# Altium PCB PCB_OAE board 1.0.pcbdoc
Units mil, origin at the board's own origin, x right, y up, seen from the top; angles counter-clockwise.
Board outline 3923.56 x 3666.58 mil, 2 copper layers (Top Layer, Bottom Layer); 47 components, 66 nets, 220 pads, 117 vias.
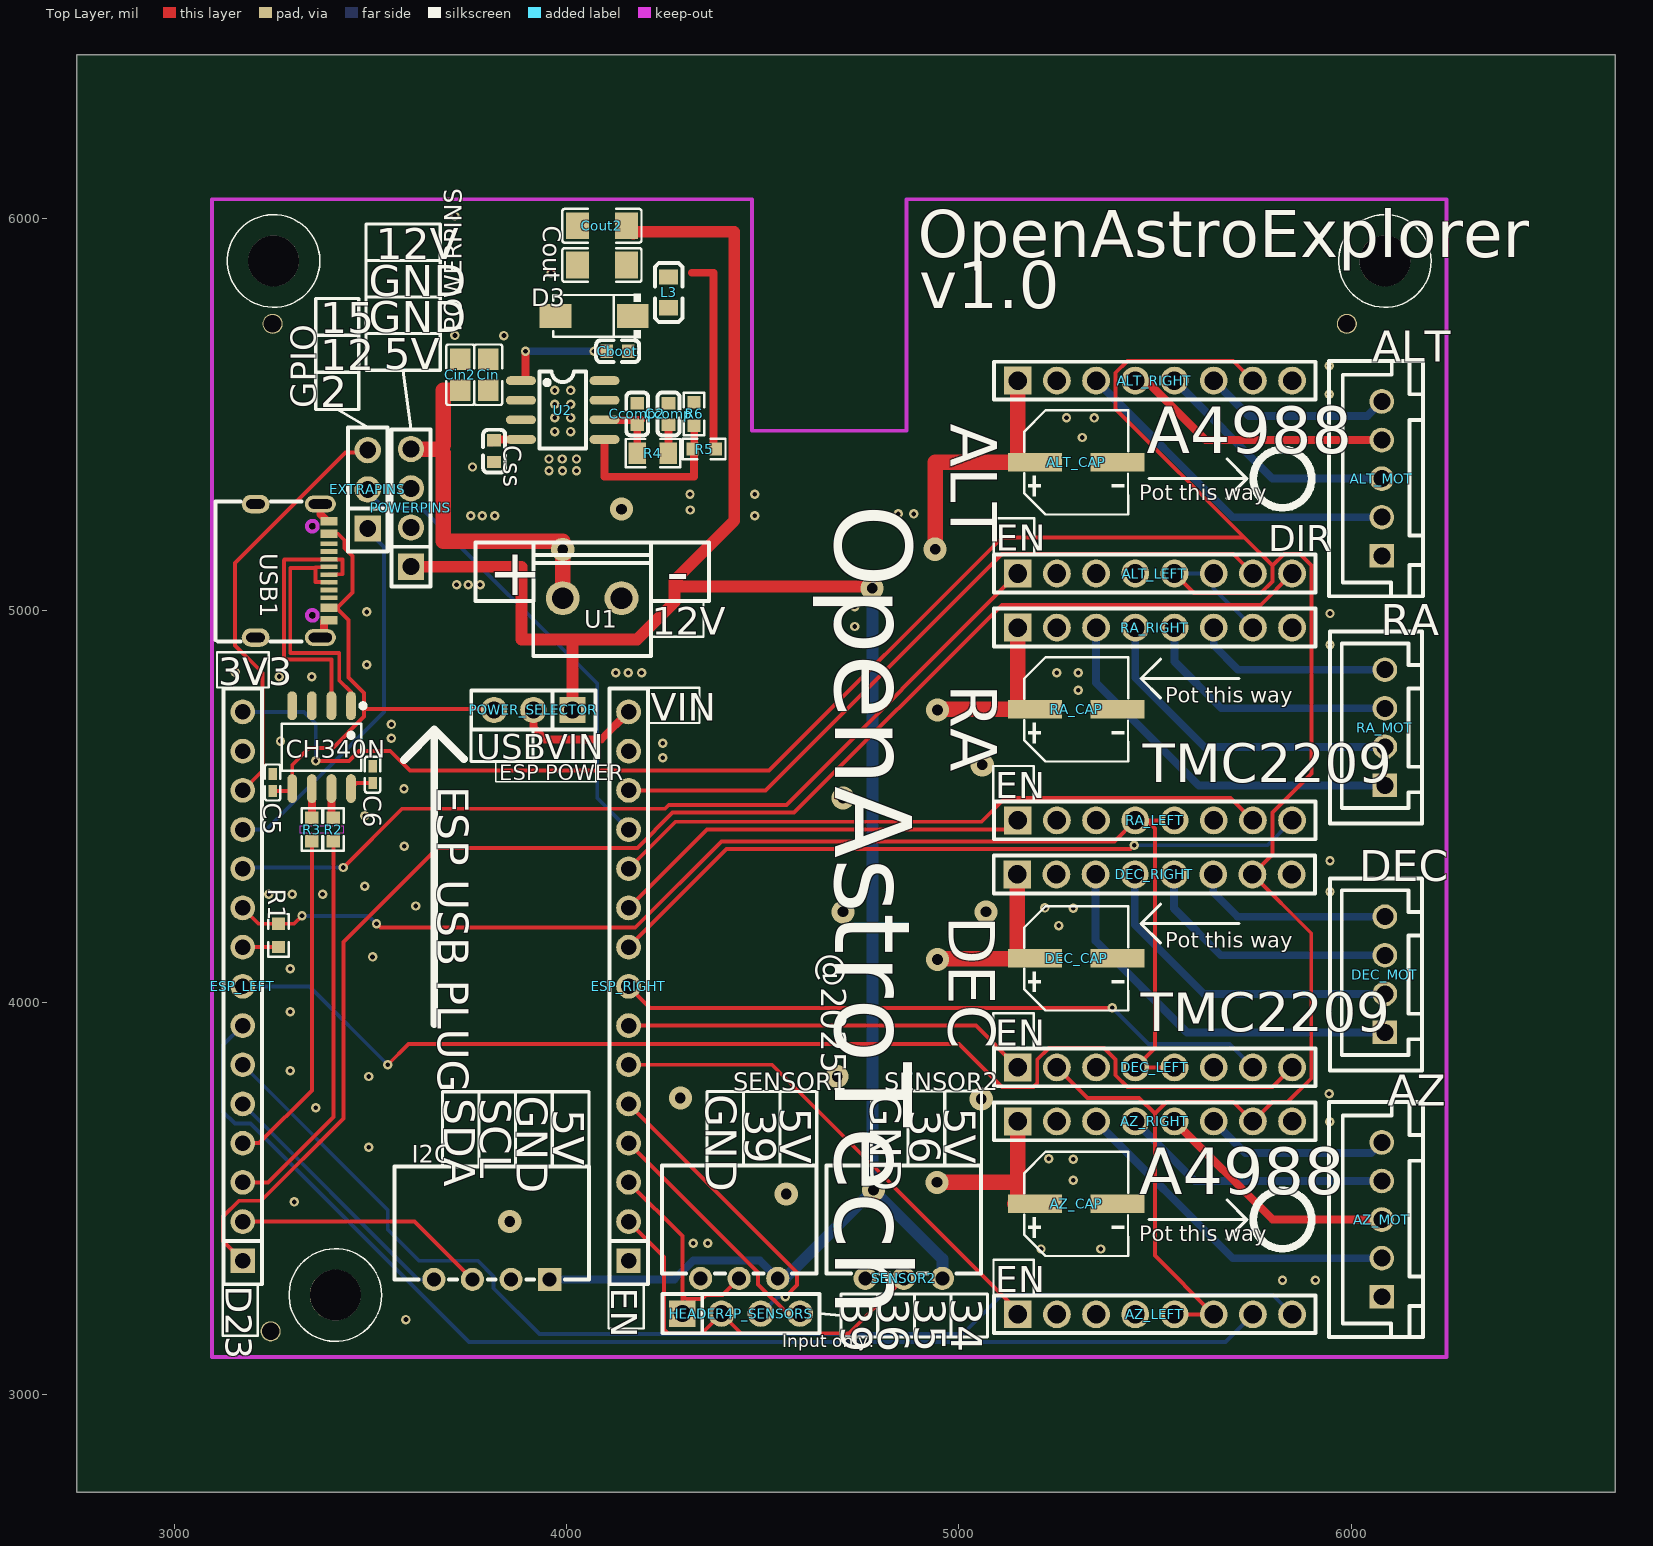
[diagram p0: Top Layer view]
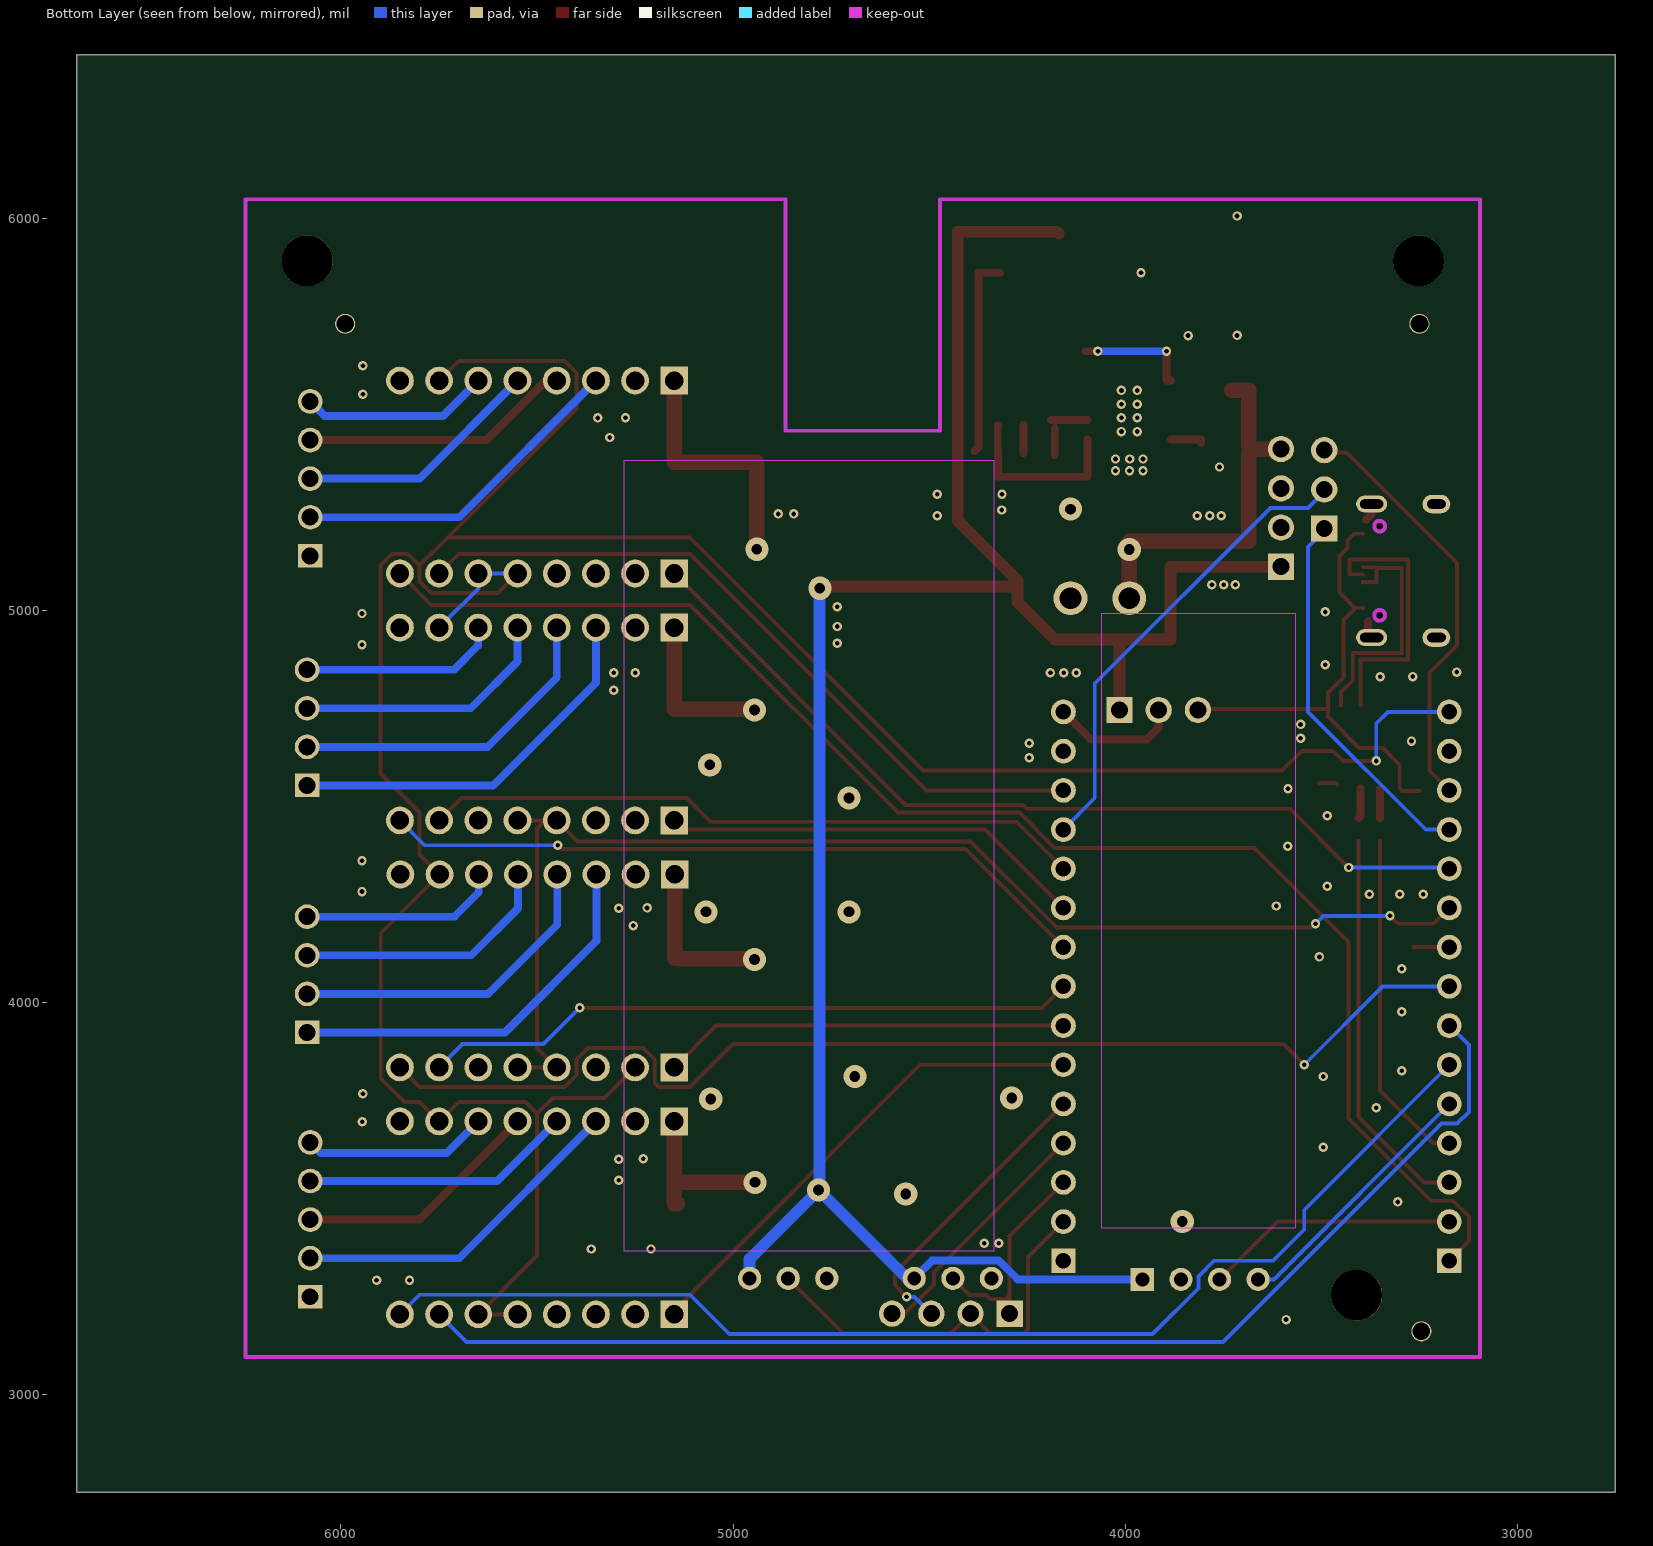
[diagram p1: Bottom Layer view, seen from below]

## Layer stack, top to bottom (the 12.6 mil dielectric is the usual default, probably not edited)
Top Layer: signal copper (thickness not stored)
Dielectric: dielectric 12.6, FR-4, Dk 4.8
Bottom Layer: signal copper (thickness not stored)

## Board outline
6673.56,2750 2750,2750 2750,6416.58 6673.56,6416.58

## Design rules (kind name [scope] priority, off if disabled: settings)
BoardOutlineClearance safeClearance [All] p0: genericclearance=10 ignorepadtopadclearanceinfootprint=FALSE except(0: Arc-SplitContinuation Track-SplitContinuation SMDPad-SplitContinuation THPad-SplitContinuation Via-SplitContinuation Fill-SplitContinuation Poly-SplitContinuation Region-SplitContinuation Text-SplitContinuation; 6: Track-CutoutEdge SMDPad-CutoutEdge THPad-CutoutEdge Via-CutoutEdge Fill-CutoutEdge Region-CutoutEdge; 11.8: Track-OutlineEdge SMDPad-OutlineEdge THPad-OutlineEdge Via-OutlineEdge Fill-OutlineEdge Region-OutlineEdge Poly-OutlineEdge Text-OutlineEdge)
Clearance safeClearance [(InNet('DEC_DIR') OR InNet('5V2A') OR InNet('ALT_EN') OR InNet('AZ_B2') OR InNet('AZ_A1') OR InNet('ALT_A1') OR InNet('ALT_B1') OR InNet('DEC_EN') OR InNet('AZ_DIR') OR InNet('ALT_DIR') OR InNet('DEC_STEP') OR InNet('AZ_EN') OR InNet('ALT_STEP') OR InNet('ESPRX') OR InNet('ESPTX') OR InNet('USBDP') OR InNet('AZ_A2') OR InNet('AZ_B1') OR InNet('ALT_B2') OR InNet('ALT_A2') OR InNet('DEC_B2') OR InNet('DEC_B1') OR InNet('DEC_A1') OR InNet('DEC_A2') OR InNet('RA_B1') OR InNet('RA_A2') OR InNet('RA_A1') OR InNet('RA_B2') OR InNet('USB5V') OR InNet('USBDN') OR InNet('ALT_MS1') OR InNet('ALT_MS2') OR InNet('ALT_MS3') OR InNet('AZ_MS1') OR InNet('AZ_MS2') OR InNet('AZ_MS3') OR InNet('DEC_CLK') OR InNet('RA_CLK') OR InNet('GPIO15') OR InNet('GPIO2') OR InNet('GPIO12') OR InNet('GPIO35') OR InNet('GPIO34') OR InNet('GPIO39') OR InNet('GPIO36') OR InNet('ESP_EN') OR InNet('AZ_STEP') OR InNet('$1N15') OR InNet('DEC_UART1') OR InNet('$1N26') OR InNet('$1N27') OR InNet('GND') OR InNet('PSU12V') OR InNet('ESPVOUT') OR InNet('GPIO17') OR InNet('GPIO21') OR InNet('GPIO22') OR InNet('$1N13245') OR InNet('$1N13249') OR InNet('$1N12989') OR InNet('$1N13607') OR InNet('$1N13151') OR InNet('$1N13891') OR InNet('GPIO14') OR InNet('GPIO26') OR InNet('GPIO27'))] p1: gap=7 ignorepadtopadclearanceinfootprint=FALSE except(6: Track-Track SMDPad-SMDPad Track-THPad SMDPad-THPad THPad-THPad Track-Via SMDPad-Via THPad-Via Via-Via Track-Fill SMDPad-Fill THPad-Fill Via-Fill Fill-Fill Track-Region SMDPad-Region THPad-Region Via-Region Fill-Region Region-Region Track-Poly SMDPad-Poly THPad-Poly Via-Poly Fill-Poly Region-Poly Poly-Poly Track-Text SMDPad-Text THPad-Text Via-Text Fill-Text Region-Text Poly-Text Text-Text; 6.9: Track-Hole SMDPad-Hole THPad-Hole Via-Hole Fill-Hole Region-Hole Poly-Hole Text-Hole Sheet-Hole; 7.9: Track-SMDPad; 11.8: Track-Sheet SMDPad-Sheet THPad-Sheet Via-Sheet Fill-Sheet Region-Sheet Poly-Sheet Text-Sheet)
DiffPairsRouting differentialPair [All] p1: maxuncoupledlength=10 minlimit=5.9843 maxlimit=5.9843 mostfreqgap=5.9843 toplayer_minwidth=5 toplayer_prefwidth=10 toplayer_maxwidth=100 bottomlayer_minwidth=5 bottomlayer_prefwidth=10 bottomlayer_maxwidth=100
PasteMaskExpansion pasteMaskExpansion [All] p1: expansion=0
PlaneConnect innerPlane [All] p1: planeconnectstyle=Relief reliefexpansion=20 reliefentries=4 reliefconductorwidth=10 reliefairgap=10
PolygonConnect copperRegion [All] p1: connectstyle=Relief reliefentries=4 reliefconductorwidth=10 polygonreliefangle="90 Angle" airgapwidth=10
PolygonConnect gge19473 [All] p1: connectstyle=Relief reliefentries=4 reliefconductorwidth=10 polygonreliefangle="90 Angle" airgapwidth=10
PolygonConnect copperRegion1 [All] p1: connectstyle=Direct reliefentries=4 reliefconductorwidth=20 polygonreliefangle="90 Angle" airgapwidth=10
PolygonConnect copperRegion2 [All] p1: connectstyle=Direct reliefentries=4 reliefconductorwidth=10 polygonreliefangle="90 Angle" airgapwidth=10
RoutingVias viaSize [All] p1: viastyle="Through Hole" holewidth=12.0078 minholewidth=11.811 maxholewidth=236.1812 width=24.0158 minwidth=19.685 maxwidth=393.7008
SolderMaskExpansion solderMaskExpansion [All] p1: useseparateexpansions=TRUE expansion=2.0079 expansionbottom=2.0079
Width trackWidth [All] p1: maxlimit=100 minlimit=5 preferedwidth=10

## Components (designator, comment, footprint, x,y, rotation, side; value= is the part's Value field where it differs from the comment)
ALT_CAP "100uF" CAP-SMD_BD6.3-L6.6-W6.6-LS7.4-FD 5298.95,5377.15 r0 top
ALT_LEFT "Header-Female-2.54_1x8" HDR-TH_8P-P2.54-V-F-1 5499.67,5093.76 r0 top
ALT_MOT "ZX-XH2.54-5PZZ" CONN-TH_5P-P2.50_ZX-XH2.54-5PZZ 6078.48,5335.74 r90 top
ALT_RIGHT "Header-Female-2.54_1x8" HDR-TH_8P-P2.54-V-F-1 5499.67,5585.88 r0 top
AZ_CAP "100uF" CAP-SMD_BD6.3-L6.6-W6.6-LS7.4-FD 5298.95,3485.74 r0 top
AZ_LEFT "Header-Female-2.54_1x8" HDR-TH_8P-P2.54-V-F-1 5499.67,3204 r0 top
AZ_MOT "ZX-XH2.54-5PZZ" CONN-TH_5P-P2.50_ZX-XH2.54-5PZZ 6078.48,3445.74 r90 top
AZ_RIGHT "Header-Female-2.54_1x8" HDR-TH_8P-P2.54-V-F-1 5499.67,3696.12 r0 top
C5 "100nF" C0402 3249.23,4560.74 r270 top
C6 "100nF" C0402 3504.23,4580.74 r90 top
Cboot "CC0603KRX7R9BB104" C0603 4129.23,5660.74 r0 top locked
Ccomp "CL10B102KB8NNNC" C0603 4259.23,5500.74 r270 top locked
Ccomp2 "CL10C100JB8NNNC" C0603 4179.23,5500.74 r270 top locked
CH340N "CH340N_C2977777" SOP-8_L4.9-W3.9-P1.27-LS6.0-BL 3374.23,4650.74 r180 top
Cin "CL21A226MAQNNNE" C0805 3799.23,5600.74 r270 top locked
Cin2 "CL21A226MAQNNNE" C0805 3727.82,5600.74 r270 top locked
Cout "CL31A476MPHNNNE" C1206 4089.23,5880.74 r0 top locked
Cout2 "CL31A476MPHNNNE" C1206 4089.23,5980.74 r0 top locked
Css "0603B822K500NT" C0603 3814.23,5405.74 r270 top locked
D3 "SS54_C22452" SMA_L4.4-W2.8-LS5.4-R-RD 4069.23,5750.74 r180 top locked
DEC_CAP "100uF" CAP-SMD_BD6.3-L6.6-W6.6-LS7.4-FD 5298.95,4112.15 r0 top
DEC_LEFT "Header-Female-2.54_1x8" HDR-TH_8P-P2.54-V-F-1 5499.67,3833.92 r0 top
DEC_MOT "ZX-XH2.54-4PZZ" CONN-TH_4P-P2.50_4PIN 6086.35,4070.74 r90 top
DEC_RIGHT "Header-Female-2.54_1x8" HDR-TH_8P-P2.54-V-F-1 5498.46,4326.04 r0 top
ESP_LEFT "FH2.54-09-15PZD" HDR-TH_15P-P2.54-V-F-1 3172.97,4040.64 r90 top
ESP_RIGHT "FH2.54-09-15PZD" HDR-TH_15P-P2.54-V-F-1 4157.22,4040.64 r90 top
EXTRAPINS "PZ254V-11-03P_C2937625" HDR-TH_3P-P2.54-V-M 3491.87,5308.34 r90 top
HEADER4P_SENSORS "PZ254V-11-04P" HDR-TH_4P-P2.54-V-M 4444.23,3205.74 r0 top
I2C "ZX-XH2.54-4PWZ" CONN-TH_4P-P2.50_ZX-XH2.54-4PWZ 3808.12,3293.19 r180 top
L3 "MLZ2012N6R8LT000" IND-SMD_L2.0-W1.3 4259.23,5810.74 r90 top locked
POWER_SELECTOR "PZ254V-11-03P_C2937625" HDR-TH_3P-P2.54-V-M 3914.23,4745.74 r180 top
POWERPINS "PZ254V-11-04P" HDR-TH_4P-P2.54-V-M 3602.1,5261.09 r90 top
R1 "1k" R0603 3264.23,4170.74 r270 top
R2 "1k" R0603 3404.23,4440.74 r90 top
R3 "1k" R0603 3349.23,4440.74 r90 top
R4 "0805W8F6202T5E" R0805 4219.23,5400.74 r180 top locked
R5 "0603WAF1002T5E" R0603 4349.9,5411.15 r0 top
R6 "0603WAF2001T5E" R0603 4324.23,5500.74 r270 top locked
RA_CAP "100uF" CAP-SMD_BD6.3-L6.6-W6.6-LS7.4-FD 5298.95,4747.15 r0 top
RA_LEFT "Header-Female-2.54_1x8" HDR-TH_8P-P2.54-V-F-1 5499.67,4463.84 r0 top
RA_MOT "ZX-XH2.54-4PZZ" CONN-TH_4P-P2.50_4PIN 6086.35,4700.74 r90 top
RA_RIGHT "Header-Female-2.54_1x8" HDR-TH_8P-P2.54-V-F-1 5499.67,4955.96 r0 top
SENSOR1 "ZX-XH2.54-3PWZ" HDR-TH_3P-P2.50_ZX-XH2.54-3PWZ 4439.23,3295.74 r180 top
SENSOR2 "ZX-XH2.54-3PWZ" HDR-TH_3P-P2.50_ZX-XH2.54-3PWZ 4859.23,3295.74 r180 top
U1 "XY303V-3.81-2P" CONN-TH_XY303V-3.81-2P 4064.23,5030.74 r180 top
U2 "TPS54331DR" SOIC-8_L5.0-W4.0-P1.27-LS6.0-BL 3989.23,5510.74 r270 top locked
USB1 "TYPE-C 16PIN 2MD(073)" USB-C-SMD_TYPE-C-6PIN-2MD-073 3299.23,5100.74 r270 top

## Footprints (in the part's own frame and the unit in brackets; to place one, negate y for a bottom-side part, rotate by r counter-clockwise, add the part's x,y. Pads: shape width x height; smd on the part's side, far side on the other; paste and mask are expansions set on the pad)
C0402 [mm]
  rect 0.79x0.54 smd: 1(-0.545,0) 2(0.545,0)
  silkscreen extent -1.17,-0.5 1.17,0.5
C0603 [mm]
  rect 0.8x0.9 smd: 1(-0.7,0) 2(0.7,0)
  silkscreen extent -1.39,-0.71 1.39,0.71
C0805 [mm]
  rect 1.41x1.35 smd: 1(-1,0) 2(1,0)
  silkscreen extent -1.96,-0.9 1.96,0.9
C1206 [mm]
  rect 1.485x1.728 smd: 1(-1.593,0) 2(1.593,0)
  silkscreen extent -2.56,-1.09 2.56,1.09
CAP-SMD_BD6.3-L6.6-W6.6-LS7.4-FD [mm]
  rect 3.5x1.2 smd: 1(-2.67,0) 2(2.67,0)
  silkscreen extent -3.38,-3.38 3.38,3.38
CONN-TH_4P-P2.50_4PIN [mm]
  rect 1.524x1.6 hole 1.1: 1(-3.75,0)
  round 1.6 hole 1.1: 2(-1.25,0) 3(1.25,0) 4(3.75,0)
  silkscreen extent -6.22,-2.41 6.22,3.56
CONN-TH_4P-P2.50_ZX-XH2.54-4PWZ [mm]
  rect 1.524x1.5 hole 0.9: 1(-3.75,0)
  round 1.5 hole 0.9: 2(-1.25,0) 3(1.25,0) 4(3.75,0)
  silkscreen extent -6.3,-7.32 6.3,0
CONN-TH_5P-P2.50_ZX-XH2.54-5PZZ [mm]
  rect 1.524x1.6 hole 1.1: 1(-5,0)
  round 1.6 hole 1.1 copper offset 0,0: 2(-2.5,0) 4(2.5,0) 5(5,0)
  round 1.6 hole 1.1: 3(0,0)
  silkscreen extent -7.62,-2.68 7.62,3.42
CONN-TH_XY303V-3.81-2P [mm]
  round 2.2 hole 1.4: 1(-1.905,0) 2(1.905,0)
  silkscreen extent -3.82,-3.6 3.82,3.75
HDR-TH_3P-P2.50_ZX-XH2.54-3PWZ [mm]
  round 1.5 hole 0.9: 1(-2.5,0) 2(0,0) 3(2.5,0)
  silkscreen extent -5,-7.32 5,-0.32
HDR-TH_3P-P2.54-V-M [mm]
  rect 1.7x1.7 hole 1.1: 1(-2.54,0)
  round 1.7 hole 1.1: 2(0,0) 3(2.54,0)
  silkscreen extent -4.02,-1.27 4.02,1.27
HDR-TH_4P-P2.54-V-M [mm]
  rect 1.7x1.7 hole 1.1: 1(-3.81,0)
  round 1.7 hole 1.1: 2(-1.27,0) 3(1.27,0) 4(3.81,0)
  silkscreen extent -5.08,-1.27 5.08,1.27
HDR-TH_8P-P2.54-V-F-1 [mm]
  rect 1.8x1.8 hole 1.2: 1(-8.89,0)
  round 1.8 hole 1.2: 2(-6.35,0) 3(-3.81,0) 4(-1.27,0) 5(1.27,0) 6(3.81,0) 7(6.35,0) 8(8.89,0)
  silkscreen extent -10.41,-1.22 10.41,1.22
HDR-TH_15P-P2.54-V-F-1 [mm]
  rect 1.6x1.575 hole 1: 1(-17.78,0)
  round 1.6 hole 1: 2(-15.24,0) 3(-12.7,0) 4(-10.16,0) 5(-7.62,0) 6(-5.08,0) 7(-2.54,0) 8(0,0) 9(2.54,0) 10(5.08,0) 11(7.62,0) 12(10.16,0) 13(12.7,0) 14(15.24,0) 15(17.78,0)
  silkscreen extent -19.3,-1.25 19.3,1.25
IND-SMD_L2.0-W1.3 [mm]
  rect 1x1.25 smd: 1(-1,0) 2(1,0)
  silkscreen extent -1.91,-0.89 1.91,0.89
R0603 [mil]
  rect 31.75x34.02 smd: 1(-29.66,0) 2(29.66,0)
  silkscreen extent -55,-26 55,26
R0805 [mm]
  rect 1.133x1.377 smd: 1(-1,0) 2(1,0)
  silkscreen extent -1.76,-0.92 1.76,0.92
SMA_L4.4-W2.8-LS5.4-R-RD [mil]
  rect 81.2x60.59 smd: 1(98.57,0) 2(-98.57,0)
  silkscreen extent -119,-56 104,56
SOIC-8_L5.0-W4.0-P1.27-LS6.0-BL [mil]
  oval 22.38x76.78 smd: 1(-75,-106.5) 2(-25,-106.5) 3(25,-106.5) 4(75,-106.5) 5(75,106.5) 6(25,106.5) 7(-25,106.5) 8(-75,106.5)
  silkscreen extent -98,-59 98,59
SOP-8_L4.9-W3.9-P1.27-LS6.0-BL [mm]
  oval 0.63x1.865 smd: 1(-1.905,-2.682) 2(-0.635,-2.682) 3(0.635,-2.682) 4(1.905,-2.682) 5(1.905,2.682) 6(0.635,2.682) 7(-0.635,2.682) 8(-1.905,2.682)
  silkscreen extent -2.82,-2.83 2.58,1.52
USB-C-SMD_TYPE-C-6PIN-2MD-073 [mm]
  rect 0.55x1.1 smd: 1(-3.2,2.375) 2(-2.4,2.375) 11(2.4,2.375) 12(3.2,2.375)
  rect 0.3x1.1 smd: 3(-1.75,2.375) 4(-1.25,2.375) 5(-0.75,2.375) 6(-0.25,2.375) 7(0.25,2.375) 8(0.75,2.375) 9(1.25,2.375) 10(1.75,2.375)
  oval 1.2x1.8 hole 0.6 slot 1.2 at 90 deg: 13(-4.325,-2.375) 14(4.325,-2.375)
  oval 1.1x2 hole 0.6 slot 1.5 at 90 deg: 13(-4.325,1.825) 14(4.325,1.825)
  Board Outline Layer circle w0.005: c-2.89,1.305 r0.35
  Board Outline Layer circle w0.005: c2.89,1.305 r0.35
  Board Outline Layer circle w0.254: c-2.89,1.305 r0.35
  Board Outline Layer circle w0.254: c2.89,1.305 r0.35
  Multi-Layer board cut-out: -2.89,1.655 -3.063,1.607 -3.189,1.479 -3.235,1.305 -3.189,1.131 -3.063,1.003 -2.89,0.955 -2.89,0.955 -2.717,1.003 -2.59,1.131 -2.544,1.305 -2.59,1.479 -2.717,1.607 -2.89,1.655
  Multi-Layer board cut-out: 2.89,1.655 2.717,1.607 2.591,1.479 2.545,1.305 2.591,1.131 2.717,1.003 2.89,0.955 2.89,0.955 3.063,1.003 3.19,1.131 3.236,1.305 3.19,1.479 3.063,1.607 2.89,1.655
  silkscreen extent -4.5,-4.97 4.57,0.6

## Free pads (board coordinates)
  round 51.18 hole 45.35 unplated: 1(3244.23,3160.74) 1(3249.23,5730.74) 1(5989.23,5730.74)
  round 129.92 hole 129.92: 1(3251.71,5891.01) 1(3409.19,3253.22) 1(6086.35,5891.01)

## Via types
v1: diameter 24.02, hole 12.01, Top Layer to Bottom Layer, 100 vias
v2: diameter 59.06, hole 27.56, Top Layer to Bottom Layer, 17 vias

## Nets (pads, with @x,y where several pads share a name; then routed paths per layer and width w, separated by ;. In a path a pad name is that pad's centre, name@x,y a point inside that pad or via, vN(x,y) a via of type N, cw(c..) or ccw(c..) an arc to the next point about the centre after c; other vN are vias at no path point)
5V2A: Cout2.2 Cout.2 ESP_RIGHT.15 I2C.1 L3.2 POWER_SELECTOR.1 POWER_SELECTOR.2 POWERPINS.1 R5.2 SENSOR1.1 SENSOR2.1 | length 6490.1
  Top Layer w20: POWER_SELECTOR.2 3914.23,4700.74 3944.23,4670.74 4087.32,4670.74 ESP_RIGHT.15 ; 4319.23,5860.74 4374.14,5860.74 4374.14,5415.48 R5.2@4383.89,5405.74
  Top Layer w30: POWERPINS.1 3884.23,5111.09 3884.23,4925.74 4014.23,4925.74 ; POWER_SELECTOR.1 4014.23,4925.74 ; Cout2.2@4169.23,5960.74 4174.23,5965.74 4426.92,5965.74 4426.92,5228.43 4274.23,5075.74 4274.23,5060.74 ; v2@4779.23,5060.74 4274.23,5060.74 ; 4014.23,4925.74 4179.23,4925.74 4274.23,5020.74 4274.23,5060.74
  Bottom Layer w20: I2C.1 4273.89,3293.19 4321.95,3341.25 4492.14,3341.25 SENSOR1.1
  Bottom Layer w30: SENSOR1.1 4556.17,3295.74 v2(4781.65,3521.21) ; v2@4779.23,5060.74 4779.23,3523.63 v2(4781.65,3521.21) ; SENSOR2.1 4957.65,3345.2 v2(4781.65,3521.21)
  other v2: 4778.51,5056.17
$1N15: C6.1 CH340N.8 | length 46.7
  Top Layer w10: CH340N.8@3459.23,4555.13 3463.38,4559.28 C6.1
$1N26: CH340N.7 R2.2 | length 76.8
  Top Layer w20: CH340N.7 3399.23,4475.4 R2.2
$1N27: CH340N.6 R3.2 | length 74.7
  Top Layer w20: R3.2 CH340N.6
$1N12989: Ccomp2.2 R4.2 U2.6 | length 188.9
  Top Layer w10: Ccomp2.2@4166.67,5485.74 Ccomp2.2 Ccomp2.2@4179.23,5463.18 ; R4.2@4179.23,5401.37 R4.2
  Top Layer w20: U2.6 4166.67,5485.74 Ccomp2.2@4188.5,5485.74 ; R4.2@4179.23,5395.74 4179.23,5401.37 Ccomp2.2@4179.23,5463.18
$1N13151: Ccomp.2 R4.1 | length 74
  Top Layer w10: R4.1 R4.1@4259.23,5401.37
  Top Layer w20: R4.1 4259.23,5400.74 4259.23,5401.37 Ccomp.2
$1N13245: Cboot.1 U2.1 | length 293.9
  Top Layer w20: U2.1 3894.23,5585.74 v1(3894.23,5660.74) ; v1(4069.23,5660.74) Cboot.1
  Bottom Layer w20: v1(3894.23,5660.74) v1(4069.23,5660.74)
$1N13249: Cboot.2 D3.2 L3.1 U2.8
$1N13607: R5.1 R6.2 U2.5 | length 455.5
  Top Layer w10: R5.1@4324.23,5394.24 R5.1@4324.57,5394.58 ; R6.2 R6.2@4324.57,5470.74
  Top Layer w20: U2.5 4095.73,5340.74 4324.23,5340.74 4324.23,5394.24 4324.23,5405.74 4324.57,5405.74 4324.57,5470.74 4324.57,5471.08 R6.2
$1N13891: Css.1 U2.4 | length 87.4
  Top Layer w10: Css.1 Css.1@3816.67,5435.74
  Top Layer w20: Css.1@3806.44,5428.06 3806.44,5435.74 3816.67,5435.74 U2.4
ALT_A1: ALT_MOT.4 ALT_RIGHT.4 | length 691.7
  Top Layer w20: ALT_RIGHT.4 5476.95,5585.88 5628.67,5434.17 ALT_MOT.4
ALT_A2: ALT_MOT.2 ALT_RIGHT.3 | length 873.2
  Bottom Layer w20: ALT_RIGHT.3 5698.23,5237.32 ALT_MOT.2
ALT_B1: ALT_MOT.3 ALT_RIGHT.5 | length 632.4
  Bottom Layer w20: ALT_RIGHT.5 5799.81,5335.74 ALT_MOT.3
ALT_B2: ALT_MOT.5 ALT_RIGHT.6 | length 481.4
  Bottom Layer w20: ALT_RIGHT.6 5702.95,5532.6 5739.81,5495.74 6041.62,5495.74 ALT_MOT.5
ALT_DIR: ALT_LEFT.8 ESP_LEFT.1 | length 3803.4
  Top Layer w10: ESP_LEFT.1 3122.97,3390.64 3122.97,3453.76 3162.97,3493.76 3219.67,3493.76 3429.67,3703.76 3429.67,4153.76 3669.67,4393.76 4179.67,4393.76 4269.67,4483.76 4579.67,4483.76 5109.67,5013.76 5769.67,5013.76 ALT_LEFT.8
ALT_EN: ALT_LEFT.1 ESP_LEFT.11 | length 2288.7
  Top Layer w10: v1(3429.67,4343.76) 3579.67,4493.76 4249.67,4493.76 4259.67,4503.76 4559.67,4503.76 ALT_LEFT.1
  Bottom Layer w10: ESP_LEFT.11 3176.09,4343.76 v1(3429.67,4343.76)
ALT_MS1: ALT_LEFT.2
ALT_MS2: ALT_LEFT.3
ALT_MS3: ALT_LEFT.4
ALT_STEP: ALT_LEFT.7 ESP_RIGHT.13 | length 1863
  Top Layer w10: ESP_RIGHT.13 4506.55,4540.64 5109.67,5143.76 5699.67,5143.76 ALT_LEFT.7
AZ_A1: AZ_MOT.4 AZ_RIGHT.4 | length 691.8
  Bottom Layer w20: AZ_RIGHT.4 5601.62,3544.17 AZ_MOT.4
AZ_A2: AZ_MOT.2 AZ_RIGHT.3 | length 873.3
  Bottom Layer w20: AZ_RIGHT.3 5698.47,3347.32 AZ_MOT.2
AZ_B1: AZ_MOT.3 AZ_RIGHT.5 | length 632.5
  Top Layer w20: AZ_RIGHT.5 5800.05,3445.74 AZ_MOT.3
AZ_B2: AZ_MOT.5 AZ_RIGHT.6 | length 473.2
  Bottom Layer w20: AZ_RIGHT.6 5703.19,3642.6 5730.05,3615.74 6051.62,3615.74 AZ_MOT.5
AZ_DIR: AZ_LEFT.8 ESP_LEFT.6 | length 3070.1
  Bottom Layer w10: ESP_LEFT.6 3542.97,3470.64 3542.97,3420.64 3622.97,3340.64 3772.97,3340.64 3812.97,3300.64 3812.97,3270.64 3929.61,3154 5009.61,3154 5109.61,3254 5799.67,3254 AZ_LEFT.8
AZ_EN: AZ_LEFT.1 ESP_RIGHT.6 | length 1262
  Top Layer w10: ESP_RIGHT.6 4523.03,3840.64 5149.67,3214 AZ_LEFT.1
AZ_MS1: AZ_LEFT.2
AZ_MS2: AZ_LEFT.3
AZ_MS3: AZ_LEFT.4
AZ_STEP: AZ_LEFT.7 ESP_LEFT.7 | length 3139.4
  Bottom Layer w10: ESP_LEFT.7 3122.97,3890.64 3122.97,3720.64 3152.97,3690.64 3192.97,3690.64 3749.61,3134 5679.67,3134 AZ_LEFT.7
DEC_A1: DEC_MOT.2 DEC_RIGHT.4 | length 839.2
  Bottom Layer w20: DEC_RIGHT.4 5448.46,4197.77 5624.7,4021.53 5732.97,4021.53 DEC_MOT.2
DEC_A2: DEC_MOT.1 DEC_RIGHT.3 | length 1004.2
  Bottom Layer w20: DEC_RIGHT.3 5348.46,4156.35 5581.71,3923.1 5686.35,3923.1 DEC_MOT.1
DEC_B1: DEC_MOT.3 DEC_RIGHT.5 | length 674.1
  Bottom Layer w20: DEC_RIGHT.5 5548.46,4239.19 5667.7,4119.95 5754.55,4119.95 DEC_MOT.3
DEC_B2: DEC_MOT.4 DEC_RIGHT.6 | length 509.1
  Bottom Layer w20: DEC_RIGHT.6 5648.46,4280.61 5710.69,4218.38 5756.12,4218.38 DEC_MOT.4
DEC_CLK: DEC_LEFT.6
DEC_DIR: DEC_LEFT.8 ESP_LEFT.8 | length 2989.3
  Top Layer w10: v1(3542.97,3840.64) 3596.25,3893.92 4999.69,3893.92 5109.69,3783.92 5189.69,3783.92 5199.69,3793.92 5199.69,3853.92 5229.69,3883.92 5369.69,3883.92 5399.69,3853.92 5399.69,3813.92 5429.69,3783.92 5799.67,3783.92 DEC_LEFT.8
  Bottom Layer w10: ESP_LEFT.8 3342.97,4040.64 v1(3542.97,3840.64)
DEC_EN: DEC_LEFT.1 ESP_RIGHT.7 | length 1036.7
  Top Layer w10: ESP_RIGHT.7 5042.95,3940.64 DEC_LEFT.1
DEC_STEP: DEC_LEFT.7 ESP_RIGHT.8 | length 1678.1
  Top Layer w10: ESP_RIGHT.8 4212.05,3985.8 v1(5391.29,3985.8)
  Bottom Layer w10: v1(5391.29,3985.8) 5483.17,3893.92 5689.67,3893.92 DEC_LEFT.7
DEC_UART1: DEC_LEFT.4 DEC_LEFT.5 ESP_LEFT.10 R1.1 RA_LEFT.4 RA_LEFT.5 | length 3286.3
  Top Layer w10: ESP_LEFT.10 3213.21,4200.4 R1.1 3304.23,4200.4 v1(3324.23,4220.4) ; v1(3514.23,4200.4) 3524.23,4190.4 4174.23,4190.4 4394.23,4410.4 5396.23,4410.4 RA_LEFT.4 RA_LEFT.4@5479.67,4463.84 ; DEC_LEFT.5 DEC_LEFT.4 5499.67,3883.92 5499.67,4443.84 RA_LEFT.4@5479.67,4463.84 ; RA_LEFT.5 RA_LEFT.4@5479.67,4463.84
  Bottom Layer w10: v1(3324.23,4220.4) 3494.23,4220.4 v1(3514.23,4200.4)
ESP_EN: ESP_RIGHT.1
ESPRX: ESP_LEFT.4 R3.1 | length 867.8
  Top Layer w10: ESP_LEFT.4 3214.46,3640.64 3349.23,3775.4 3349.23,3816.9 R3.1
ESPTX: ESP_LEFT.3 R2.1 | length 1003.9
  Top Layer w10: ESP_LEFT.3 3237.25,3540.64 3404.23,3707.62 3404.23,3771.9 R2.1
ESPVOUT: ALT_LEFT.5 ALT_LEFT.6 ALT_RIGHT.7 AZ_LEFT.5 AZ_LEFT.6 AZ_RIGHT.7 DEC_LEFT.2 DEC_RIGHT.7 ESP_LEFT.15 RA_RIGHT.7 | length 7590.8
  Top Layer w10: v1(3359.23,4615.74) 3444.23,4615.74 3469.23,4640.74 3549.23,4640.74 3599.23,4590.74 4515.38,4590.74 5110.38,5185.74 5727.69,5185.74 ; DEC_LEFT.2 5327.46,3756.12 5459.67,3756.12 5499.67,3716.12 ; AZ_LEFT.5 AZ_LEFT.6 5499.67,3354 5499.67,3716.12 ; ALT_LEFT.5 5599.67,5043.76 5769.67,5043.76 5799.67,5073.76 5799.67,5113.76 ; ALT_RIGHT.7 5699.67,5635.88 5429.67,5635.88 5399.67,5605.88 5399.67,5513.76 5727.69,5185.74 ; 5499.67,3716.12 5529.67,3746.12 5699.67,3746.12 AZ_RIGHT.7 5799.59,3746.04 5838.46,3746.04 5898.46,3806.04 5898.46,4176.04 DEC_RIGHT.7 5799.67,4377.25 5799.67,4483.76 5899.67,4583.76 5899.67,5113.76 5869.67,5143.76 5829.67,5143.76 5799.67,5113.76 ; 5727.69,5185.74 5799.67,5113.76
  Bottom Layer w10: ESP_LEFT.15 3329.33,4740.64 3359.23,4710.74 v1(3359.23,4615.74) ; ALT_LEFT.5 ALT_LEFT.6 5649.67,5055.96 RA_RIGHT.7
GND: ALT_CAP.2 ALT_RIGHT.2 ALT_RIGHT.8 AZ_CAP.2 AZ_RIGHT.2 AZ_RIGHT.8 C5.1 C6.2 Ccomp2.1 Ccomp.1 CH340N.3 Cin2.1 Cin.1 Cout2.1 Cout.1 Css.2 D3.1 DEC_CAP.2 DEC_LEFT.3 DEC_RIGHT.2 DEC_RIGHT.8 ESP_LEFT.14 ESP_RIGHT.14 I2C.2 POWERPINS.2 POWERPINS.3 R6.1 RA_CAP.2 RA_LEFT.2 RA_LEFT.3 RA_RIGHT.2 RA_RIGHT.8 SENSOR1.3 SENSOR2.3 U1.1 U2.7 USB1.1 USB1.12 USB1.13 USB1.14 | length 89.6
  Top Layer w20: USB1.14@3369.66,4930.5 3380.5,4941.34 USB1.12@3380.5,4970.93 ; USB1.13@3371.42,5270.03 3371.42,5244.83 USB1.1@3385.19,5231.06
  other v1: 3589.23,3190.74 5825.13,3290.74 5909.23,3290.74 5209.23,3370.74 5361.64,3370.74 4322.22,3385.74 4359.23,3385.74 3304.23,3490.74 5291.24,3545.74 5291.24,3599.63 5229.23,3600.74 3494.23,3630.43 5945.88,3695.39 3359.23,3730.74 5943.95,3767.04 3494.23,3810.74 3294.23,3825.74 3294.23,3975.74 3294.23,4085.74 3504.23,4115.74 5254.23,4195.74 5291.24,4240.07 5219.23,4240.74 3614.23,4245.74 3239.23,4275.74 3299.23,4275.74 3376.59,4275.61 5946.35,4282.47 3484.23,4295.74 5946.35,4360.91 3584.68,4397.79 3484.23,4475.74 3584.23,4544.57 4244.23,4624.12 4244.23,4660.74 3269.23,4666.29 3552.22,4673.73 3552.22,4708.73 5304.23,4795.74 3266.42,4830.87 3349.23,4830.74 4124.23,4840.74 4156.72,4840.74 4190.33,4840.74 5249.23,4840.74 5304.23,4840.74 3153.96,4842.39 3489.23,4860.74 5946.35,4911.94 4734.23,4915.74 4734.23,4958.57 5946.35,4991.69 3489.23,4995.74 4734.23,5008.99 3718.45,5064.78 3748.45,5064.78 3778.45,5064.78 3754.23,5240.74 3784.23,5240.74 3815.57,5241.18 4479.23,5241.33 4844.72,5245.74 4884.23,5245.74 4314.23,5255.74 4313.89,5296.16 4479.23,5295.74 3954.23,5355.74 3988.68,5355.74 4024.32,5355.74 3759.02,5365.4 3954.23,5385.74 3988.33,5385.74 4024.32,5385.74 5314.23,5440.74 3969.23,5455.74 4009.23,5455.74 3969.23,5490.74 4009.23,5490.74 5274.23,5490.74 5345.02,5490.54 3969.23,5525.74 4009.23,5525.74 5943.95,5551.28 3969.23,5560.74 4009.23,5560.74 5943.95,5623.79 3714.23,5701.01 3839.23,5700.74 3959.23,5860.74 3714.23,6005.74
  other v2: 3854.23,3440.74 4559.23,3510.74 5056.91,3753.21 4289.23,3755.74 4689.23,3810.74 4704.23,4230.74 5069.23,4230.74 4704.23,4520.74 5059.23,4605.74 4139.23,5257.91
GPIO2: ESP_LEFT.12 EXTRAPINS.1 | length 963.1
  Bottom Layer w10: ESP_LEFT.12 3232.97,4440.64 3532.97,4740.64 3532.97,5161.33 EXTRAPINS.1@3491.87,5202.43
GPIO12: ESP_RIGHT.12 EXTRAPINS.2 | length 1193.4
  Bottom Layer w10: EXTRAPINS.2@3491.87,5302.43 3533.66,5260.64 3629.33,5260.64 4077.22,4812.75 4077.22,4520.64 ESP_RIGHT.12
GPIO14: ESP_RIGHT.11 RA_LEFT.7 | length 1690.5
  Top Layer w10: ESP_RIGHT.11 4277.22,4460.64 5057.22,4460.64 5117.22,4520.64 5692.87,4520.64 RA_LEFT.7
GPIO15: ESP_LEFT.13 EXTRAPINS.3 | length 1085.3
  Top Layer w10: ESP_LEFT.13 3222.97,4590.64 3222.97,4840.64 3152.97,4910.64 3152.97,5120.64 3434.76,5402.43 EXTRAPINS.3@3491.87,5402.43
GPIO17: ESP_LEFT.9 R1.2 | length 91.4
  Top Layer w10: ESP_LEFT.9 3173.41,4141.08 R1.2
GPIO21: ESP_LEFT.5 I2C.4 | length 672.8
  Bottom Layer w10: ESP_LEFT.5 3620.42,3293.19 I2C.4
GPIO22: ESP_LEFT.2 I2C.3 | length 647
  Top Layer w10: ESP_LEFT.2 3611.46,3440.64 I2C.3
GPIO26: ESP_RIGHT.9 RA_LEFT.8 | length 1826.3
  Top Layer w10: ESP_RIGHT.9 4407.22,4390.64 5437.22,4390.64 v1(5447.22,4400.64)
  Bottom Layer w10: v1(5447.22,4400.64) 5786.47,4400.64 RA_LEFT.8
GPIO27: ESP_RIGHT.10 RA_LEFT.1 | length 1084.9
  Top Layer w10: ESP_RIGHT.10 4357.22,4440.64 5126.47,4440.64 RA_LEFT.1
GPIO34: ESP_RIGHT.4 HEADER4P_SENSORS.4 | length 634.7
  Top Layer w10: ESP_RIGHT.4 4487.22,3310.64 4487.22,3280.64 4562.12,3205.74 HEADER4P_SENSORS.4
GPIO35: ESP_RIGHT.5 HEADER4P_SENSORS.3 | length 763.2
  Top Layer w10: ESP_RIGHT.5 4587.22,3310.64 4587.22,3278.73 v1(4557.22,3248.73)
  Bottom Layer w10: HEADER4P_SENSORS.3 4537.22,3248.73 v1(4557.22,3248.73)
GPIO36: ESP_RIGHT.2 HEADER4P_SENSORS.2 SENSOR2.2 | length 1027.7
  Top Layer w10: ESP_RIGHT.2 4247.22,3350.64 4247.22,3165.74 4257.22,3155.74 4344.23,3155.74 HEADER4P_SENSORS.2 4444.23,3155.74 4719.23,3155.74 SENSOR2.2
GPIO39: ESP_RIGHT.3 HEADER4P_SENSORS.1 SENSOR1.2 | length 562.4
  Top Layer w10: ESP_RIGHT.3 4294.23,3403.63 4294.23,3253.63 ; HEADER4P_SENSORS.1 4294.23,3253.63 ; SENSOR1.2 4397.12,3253.63 4354.23,3253.63 4344.23,3243.63 4304.23,3243.63 4294.23,3253.63
PSU12V: ALT_CAP.1 ALT_RIGHT.1 AZ_CAP.1 AZ_RIGHT.1 Cin2.2 Cin.2 DEC_CAP.1 DEC_RIGHT.1 POWERPINS.4 RA_CAP.1 RA_RIGHT.1 U1.2 U2.2 | length 2842.3
  Top Layer w39.37: POWERPINS.4 3674.23,5411.09 ; Cin2.2 3684.23,5561.37 3684.23,5421.09 3674.23,5411.09 ; U1.2 v2(3989.23,5154.66) 3989.23,5175.74 3684.23,5175.74 3684.23,5401.09 3674.23,5411.09 ; v2(4939.23,5155.74) 4939.23,5377.15 5149.67,5377.15 ALT_RIGHT.1 ; v2(4944.23,3540.74) 5149.37,3540.74 5149.67,3540.44 ; v2@4944.23,4110.74 DEC_CAP.1@5134.78,4110.74 ; v2@4944.23,4747.15 5149.67,4747.15 RA_RIGHT.1 ; AZ_CAP.1@5142.65,3485.74 5149.67,3485.74 5149.67,3540.44 ; DEC_CAP.1@5148.02,4112.15 5148.46,4112.15 DEC_RIGHT.1 ; AZ_RIGHT.1 5149.67,3540.44
  other v2: 4945.18,4108.96 4945.18,4745.37
RA_A1: RA_MOT.2 RA_RIGHT.4 | length 837.9
  Bottom Layer w20: RA_RIGHT.4 5449.67,4827.69 5625.83,4651.53 5734.1,4651.53 RA_MOT.2
RA_A2: RA_MOT.1 RA_RIGHT.3 | length 986
  Bottom Layer w20: RA_RIGHT.3 5349.67,4815.3 5611.87,4553.1 RA_MOT.1
RA_B1: RA_MOT.3 RA_RIGHT.5 | length 672.9
  Bottom Layer w20: RA_RIGHT.5 5549.67,4869.11 5668.83,4749.95 5755.68,4749.95 RA_MOT.3
RA_B2: RA_MOT.4 RA_RIGHT.6 | length 507.9
  Bottom Layer w20: RA_RIGHT.6 5649.67,4910.53 5711.82,4848.38 5750.81,4848.38 RA_MOT.4
RA_CLK: RA_LEFT.6
USB5V: C5.2 CH340N.5 POWER_SELECTOR.3 USB1.2 USB1.11 | length 1251.7
  Top Layer w10: C5.2 3293.38,4539.28 CH340N.5 3299.23,4605.74 3342.13,4648.64 3402.74,4648.64 3482.74,4728.64 3482.74,4748.64 ; USB1.11 3392.83,5006.34 3415.04,5006.34 3415.76,5005.62 ; USB1.2 3416.16,5195.22 3432.74,5178.64 3432.74,5158.64 3452.74,5138.64 3452.74,5045.8 3415.76,5008.82 3415.76,5005.62 ; POWER_SELECTOR.3 3811.33,4748.64 3482.74,4748.64 ; 3415.76,5005.62 3415.76,5002.41 3442.74,4975.44 3442.74,4828.64 3482.74,4788.64 3482.74,4748.64
USBDN: CH340N.2 USB1.5 USB1.7 | length 716
  Top Layer w10: USB1.7 3392.74,5091.8 3424.68,5091.8 3427.27,5091.8 3427.27,5094.39 3427.27,5121.82 3427.27,5129.36 3419.73,5129.36 3286.67,5129.36 3279.23,5129.36 3279.23,5126.56 3278.24,5126.56 3278.24,5120.93 3278.24,4874.75 3399.23,4874.75 3399.23,4769.86 CH340N.2
USBDP: CH340N.1 USB1.6 USB1.8 | length 659.7
  Top Layer w10: USB1.6@3391.83,5109.67 3358.21,5109.67 3358.21,5108.08 ; USB1.8 3392.74,5072.11 3363.19,5072.11 3358.21,5072.11 3358.21,5077.09 3358.21,5105.33 3358.21,5108.08 ; CH340N.1 3449.23,4791.35 3419.23,4821.35 3419.23,4890.74 3294.23,4890.74 3294.23,5108.08 3358.21,5108.08
pads on no net: ALT_MOT.1 AZ_MOT.1 CH340N.4 U2.3 USB1.3 USB1.4 USB1.9 USB1.10

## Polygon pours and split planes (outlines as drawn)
PSU12V on Bottom Layer (solid, remove dead copper, pour order 20): 3918.47,5200.74 4989.23,5200.74 4989.23,5120.76 3918.47,5120.76
PSU12V on Bottom Layer (solid, remove dead copper, pour order 22): 3918.97,5199.49 4059.22,5199.49 4059.22,4958.68 3918.97,4958.68
PSU12V on Bottom Layer (solid, remove dead copper, pour order 24): 4845.22,5200.22 4989.01,5200.22 4989.01,3498.33 4845.22,3498.33
GND on Bottom Layer (solid, remove dead copper, pour order 26): 3034.23,6125.74 6294.23,6125.74 6294.23,3050.74 3034.23,3050.74
5V2A on Top Layer (solid, remove dead copper, pour order 8): 4139.23,6030.74 4354.23,6030.74 4354.23,5830.74 4139.23,5830.74
GND on Top Layer (solid, remove dead copper, pour order 12): 3328.67,4860.74 3369.23,4860.74 3369.23,4745.64 3328.67,4745.64
GND on Top Layer (solid, remove dead copper, pour order 14): 3106.63,5402.86 3523.86,5402.86 3523.86,4464.65 3106.63,4464.65
PSU12V on Top Layer (solid, remove dead copper, pour order 16): 3909.03,5202.34 4059.23,5202.34 4059.23,4960.74 3909.03,4960.74
GND on Top Layer (solid, remove dead copper, pour order 0): 3934.23,5707.64 4043.28,5707.64 4043.28,5315.66 4364.23,5315.66 4364.23,5216.6 3710.67,5216.6 3710.67,5390.66 3934.23,5390.66
GND on Top Layer (solid, remove dead copper, pour order 2): 4039.23,5555.74 4349.23,5555.74 4349.23,5510.74 4039.23,5510.74
$1N13249 on Top Layer (solid, remove dead copper, pour order 4): 4075.73,5573.07 4349.23,5573.07 4349.23,5790.74 4139.23,5790.74 4139.23,5615.74 4075.73,5615.74
GND on Top Layer (solid, remove dead copper, pour order 6): 4044.23,5690.74 4044.23,6030.74 3684.23,6030.74 3684.23,5620.74 3859.23,5620.74 3859.23,5690.74
PSU12V on Top Layer (solid, remove dead copper, pour order 10): 3659.23,5510.74 3659.23,5585.74 3826.77,5585.74 3826.77,5559.06 3902.25,5559.06 3902.25,5510.74
GND on Top Layer (solid, remove dead copper, pour order 18): 3005.01,6158.29 3005.01,3005.01 3000,3000 6378.52,3000 6423.56,3045.05 6423.56,6123.25 4502.4,6123.25 4499.89,6120.75 4499.89,5321.4 4492.48,5313.98 3721.31,5313.98 3703.52,5331.76 3704.5,6166.58

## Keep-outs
Top Layer:
  region: 3319.23,4450.74 3429.23,4450.74 3429.23,4430.74 3319.23,4430.74
Bottom Layer:
  region: 4334.23,5380.74 5279.23,5380.74 5279.23,3365.74 4334.23,3365.74
  region: 3564.23,4990.74 4060.75,4990.74 4060.75,3425.02 3564.23,3425.02
Board Outline Layer:
  lines w10: 4865.88,6048.49 4865.88,5457.94 4472.18,5457.94 4472.18,6048.49 3094.23,6048.49 3094.23,3095.74 6243.83,3095.74 6243.83,6048.49 ; 4865.93,6048.49 6243.88,6048.49

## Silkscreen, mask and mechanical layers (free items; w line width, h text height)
Top Silkscreen Layer:
  drawing of 165 lines, arcs and shapes, not listed
  text "OpenAstroExplorer" at 4894.23,5900.74 h120
  text "12V" at 3512.12,5895.74 h78.74
  text "GND" at 3494.84,5801.26 h78.74
  text "v1.0" at 4899.23,5770.74 h120
  text "POWERPINS" at 3732.12,5710.74 h45 r90
  text "GND" at 3494.83,5708.78 h78.74
  text "15" at 3370.51,5707.06 h78.74
  text "ALT" at 6054.04,5633.96 h78.74
  text "5V" at 3532.8,5615.08 h78.74
  text "12" at 3370.51,5612.06 h78.74
  text "2" at 3370.51,5517.36 h78.74
  text "GPIO" at 3359.23,5515.74 h62.99 r90
  text "ALT" at 4979.23,5475.74 h118.11 r270
  text "A4988" at 5479.23,5400.74 h118.11
  text "Pot this way" at 5459.23,5280.74 h39.37
  text "OpenAstroTech" at 4684.23,5270.74 h196.85 r270
  text "EN" at 5093.65,5152.41 h66.93
  text "DIR" at 5789.23,5150.74 h66.93
  text "-" at 4253.55,5040.57 h120
  text "+" at 3799.39,5037.87 h120
  text "12V" at 4216.65,4938.16 h70.87
  text "RA" at 6075.19,4936.03 h78.74
  text "RA" at 4979.23,4810.74 h118.11 r270
  text "3V3" at 3110.83,4809.29 h70.87
  text "Pot this way" at 5526.74,4763.72 h39.37
  text "VIN" at 4213.72,4718.19 h70.87
  text "USB" at 3768.55,4619.65 h62.99
  text "VIN" at 3943.55,4619.65 h62.99
  text "ESP POWER" at 3826.69,4566.17 h39.37
  text "TMC2209" at 5469.23,4560.74 h98.43
  text "ESP USB PLUG" at 3669.83,4550.58 h78.74 r270
  text "EN" at 5092.98,4519.94 h66.93
  text "DEC" at 6020.82,4308.8 h78.74
  text "DEC" at 4974.23,4220.74 h118.11 r270
  text "Pot this way" at 5526.74,4138.72 h39.37
  text "@2025" at 4649.23,4125.74 h62.99 r270
  text "TMC2209" at 5464.23,3925.74 h98.43
  text "EN" at 5092.88,3889.58 h66.93
  text "SENSOR2" at 4809.23,3775.74 h45
  text "GND" at 4354.23,3765.74 h78.74 r270
  text "GND" at 4773.92,3766.36 h78.74 r270
  text "GND" at 3871.47,3762.06 h78.74 r270
  text "SDA" at 3686.4,3755.67 h78.74 r270
  text "SCL" at 3778.99,3755.68 h78.74 r270
  text "AZ" at 6094.23,3735.74 h78.74
  text "5V" at 4544.23,3730.74 h78.74 r270
  text "5V" at 4963.92,3731.36 h78.74 r270
  text "5V" at 3964.48,3726.61 h78.74 r270
  text "39" at 4454.23,3725.74 h78.74 r270
  text "36" at 4873.92,3726.36 h78.74 r270
  text "A4988" at 5459.23,3510.74 h118.11
  text "Pot this way" at 5459.23,3390.74 h39.37
  text "D23" at 3129.36,3277.51 h66.93 r270
  text "EN" at 4112.37,3271.93 h66.93 r270
  text "EN" at 5093.09,3260.18 h66.93
  text "39" at 4700.1,3245.12 h78.74 r270
  text "36" at 4793.61,3245.12 h78.74 r270
  text "35" at 4886.87,3245.12 h78.74 r270
  text "34" at 4980.08,3245.12 h78.74 r270
  text "Input only!" at 4549.23,3119.54 h31.5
